// Mitsubishi GX Works2 project: MC-13MR-8MTS-FE700-FX2N-C例程w   PLC: FX2N/FX2NC

PROGRAM MAIN
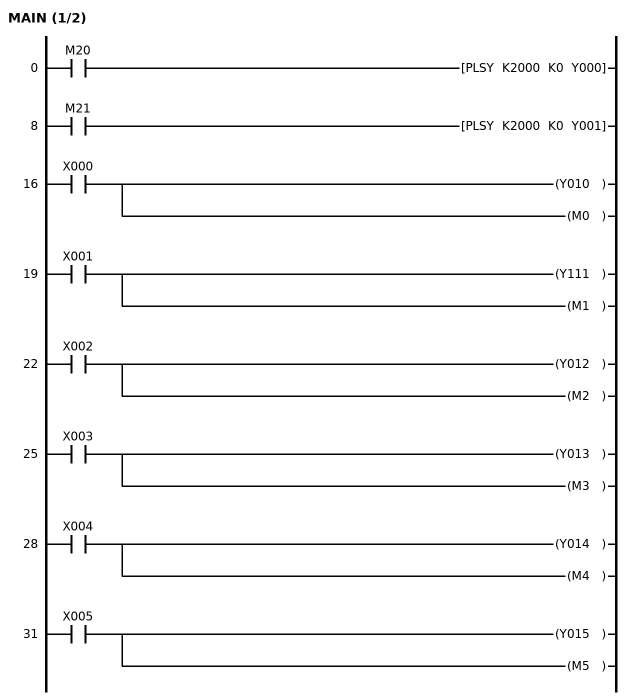
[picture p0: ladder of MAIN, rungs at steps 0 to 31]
0     LD      M20
      PLSY    K2000 K0 Y000
8     LD      M21
      PLSY    K2000 K0 Y001
16    LD      X000
      OUT     Y010
      OUT     M0
19    LD      X001
      OUT     Y111
      OUT     M1
22    LD      X002
      OUT     Y012
      OUT     M2
25    LD      X003
      OUT     Y013
      OUT     M3
28    LD      X004
      OUT     Y014
      OUT     M4
31    LD      X005
      OUT     Y015
      OUT     M5
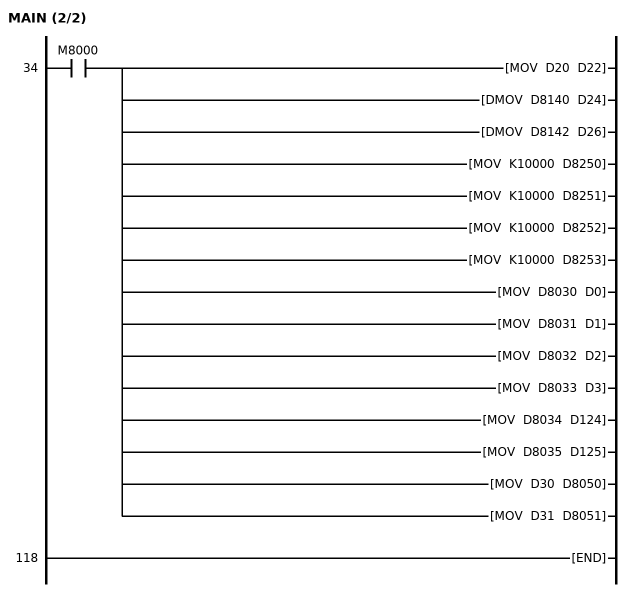
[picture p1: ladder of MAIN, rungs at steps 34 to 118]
34    LD      M8000
      MOV     D20 D22
      DMOV    D8140 D24
      DMOV    D8142 D26
      MOV     K10000 D8250
      MOV     K10000 D8251
      MOV     K10000 D8252
      MOV     K10000 D8253
      MOV     D8030 D0
      MOV     D8031 D1
      MOV     D8032 D2
      MOV     D8033 D3
      MOV     D8034 D124
      MOV     D8035 D125
      MOV     D30 D8050
      MOV     D31 D8051
118   END
END_PROGRAM
